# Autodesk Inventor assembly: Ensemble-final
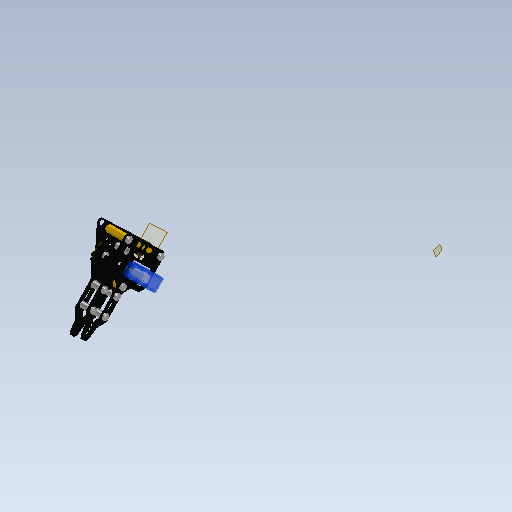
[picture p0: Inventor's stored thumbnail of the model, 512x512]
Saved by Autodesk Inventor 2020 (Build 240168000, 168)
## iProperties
Created: 2021-10
Part Number: Ensemble-final
Document SubType Name: Assembly
Designer: bruno
Mass: 18.8405 g
Surface Area: 253.631 cm^2
Volume: 12.257 cm^3
Density: 1.53711 g/cm^3
Author: bruno
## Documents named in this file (4)
- C:\Users\bruno\OneDrive\Bureau\Robot-Inventor\Robot-equillibrage\Ensemble-final.iam
- C:\Users\bruno\OneDrive\Bureau\Robot-Inventor\Robot-equillibrage\Ensemble-corps.iam
- C:\Users\bruno\OneDrive\Bureau\Robot-Inventor\Robot-equillibrage\Ensemble-pince.iam
- C:\Users\bruno\OneDrive\Bureau\Robot-Inventor\Robot-equillibrage\Ensemble-pince-2.iam
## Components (3 placed, 3 different names)
1. Ensemble-corps:1 [sub-assembly] — Placage:1, Logement:1, Angle:2
2. Ensemble-pince:1 [sub-assembly] — Placage:1, Affleurement:1, Rotation:1, Angle:1, Angle:2
3. Ensemble-pince-2:1 [sub-assembly] — Logement:1, Affleurement:1, Rotation:1, Angle:1
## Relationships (6: Angle 2, Mate 1, Insert 1, Flush 1, RelateRotation 1)
- Placage:1 [Mate]: Ensemble-corps:1 ↔ Ensemble-pince:1
- Logement:1 [Insert]: Ensemble-corps:1 ↔ Ensemble-pince-2:1
- Affleurement:1 [Flush]: Ensemble-pince:1 ↔ Ensemble-pince-2:1
- Rotation:1 [RelateRotation]: Ensemble-pince:1 ↔ Ensemble-pince-2:1
- Angle:1: Ensemble-pince:1 ↔ Ensemble-pince-2:1
- Angle:2: Ensemble-corps:1 ↔ Ensemble-pince:1
